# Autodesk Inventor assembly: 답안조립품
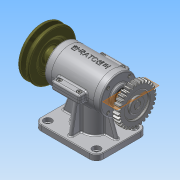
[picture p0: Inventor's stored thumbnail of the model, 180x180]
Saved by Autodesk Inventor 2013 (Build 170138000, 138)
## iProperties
Created: 2015-09
Part Number: 답안조립품
Document SubType Name: Assembly
Designer: Administrator
Author: Administrator
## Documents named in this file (17)
- C:\Users\Administrator\Desktop\350908V1020\답안조립품.iam
- C:\Users\Administrator\Desktop\350908V1020\본체.ipt
- C:\Users\Administrator\Desktop\350908V1020\M3x0.5x8.ipt
- C:\Users\Administrator\Desktop\350908V1020\M4x0.5x14.ipt
- C:\Users\Administrator\Desktop\350908V1020\V-벨트풀리.ipt
- C:\Users\Administrator\Desktop\350908V1020\가변스프링.ipt
- C:\Users\Administrator\Desktop\350908V1020\뒤커버.ipt
- C:\Users\Administrator\Desktop\350908V1020\멈춤나사.ipt
- C:\Users\Administrator\Desktop\350908V1020\베어링 6201.ipt
- C:\Users\Administrator\Desktop\350908V1020\베어링 6202.ipt
- C:\Users\Administrator\Desktop\350908V1020\본체 커버.ipt
- C:\Users\Administrator\Desktop\350908V1020\스퍼기어.ipt
- C:\Users\Administrator\Desktop\350908V1020\슬라이드.ipt
- C:\Users\Administrator\Desktop\350908V1020\앞커버.ipt
- C:\Users\Administrator\Desktop\350908V1020\오일실.ipt
- C:\Users\Administrator\Desktop\350908V1020\키4x4.ipt
- C:\Users\Administrator\Desktop\350908V1020\편심축.ipt
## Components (14 placed, 4 different names)
1. M4x0.5x14:1
2. V-벨트풀리:1 — 플러쉬:1, 각도:1
3. 가변스프링:1
4. M4x0.5x14:2
5. M4x0.5x14:3
6. M4x0.5x14:4
7. M3x0.5x8:1
8. M3x0.5x8:3
9. M3x0.5x8:4
10. M3x0.5x8:5
11. M3x0.5x8:2
12. M3x0.5x8:6
13. M3x0.5x8:7
14. M3x0.5x8:8
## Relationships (2: Flush 1, Angle 1)
- 플러쉬:1 [Flush]: V-벨트풀리:1
- 각도:1 [Angle]: V-벨트풀리:1
